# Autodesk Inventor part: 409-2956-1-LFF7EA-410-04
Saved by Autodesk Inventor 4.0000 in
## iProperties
Created: 2010-06
Part Number: 409-2956-1-LFF7EA-410-04
Cost Center: 0 lbmass
Material: A304 STAINLESS STEEL
Document SubType Name: Sheet Metal
Designer: S. Boerckel
Authority: 0 in^3
Mass: 111.23 g
Surface Area: 158.772 cm^2
Volume: 13.766 cm^3
Density: 8.08 g/cm^3
Flat Pattern Width: 10.16 cm
Flat Pattern Length: 10.16 cm
Flat Pattern Area: 103.226 cm^2
Sheet Metal Rule: 14Ga
Sheet Metal Width: 4.0000 in
Sheet Metal Length: 16.0000 in^2
Description: STRAINER 186Ga SHIM
User Status: BURN
SaveDate: 2008-01-15
SaveTime: 10:24
FileName: Sheet Metal
Wide: =<Flat Pattern Width>cm
Length: =<Flat Pattern Length>cm
Thickness: 0.0747 in
SMR: =<Sheet Metal Rule> - <Material>
Author: S. Boerckel
Revision Number: 0
Title: STRAINER 18Ga SHIM
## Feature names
1. Plate1
2. Cut1
